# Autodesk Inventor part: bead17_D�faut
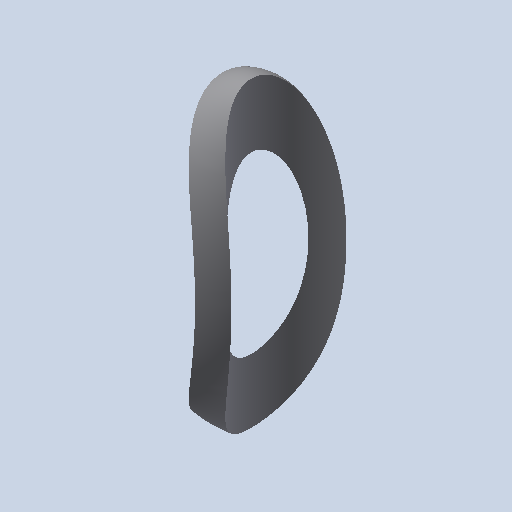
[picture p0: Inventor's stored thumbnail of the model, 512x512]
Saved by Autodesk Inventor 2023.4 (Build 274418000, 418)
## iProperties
Created: 2011-01
Part Number: bead17_D�faut
Document SubType Name: Modeling
Designer: eric
Density: 1 g/cm^3
Mass: 0.0835582 g
Surface Area: 2.71182 cm^2
Volume: 0.0835582 cm^3
Material: Générique
Appearance: Par défaut
Author: eric
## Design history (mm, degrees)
feature "Base1"
node "Corps solides"
node "Corps surfaciques"
node "Solide1"
